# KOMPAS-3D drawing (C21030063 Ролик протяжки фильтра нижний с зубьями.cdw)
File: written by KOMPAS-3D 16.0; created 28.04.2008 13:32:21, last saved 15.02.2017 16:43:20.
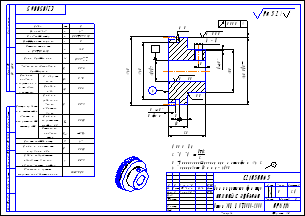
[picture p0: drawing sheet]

Sheet 1: A3, landscape

Title block, sheet 1: name: Ролик протяжки фильтра / нижний с зубьями; designation: C21030063; material: Сталь ХВГ  ГОСТ 5950-2000; mass: 0,2; sheets: 1; organisation: Орими; sheet format: A3; stored path: E:\Рабочая\Чертежи\Невские пороги\C23030129 Шестеня.cdw; drawn by: Баличев Д.С.; drawn by, date: 11.11.14

Views: Вид 1, Вид 3, Местный разрез 1, Спереди, Проекционный вид 4, Вид 5, Изометрия XYZ
Referenced files in D:\: C21030063 Ролик протяжки фильтра нижний с зубьями.m3d
Referenced files in D:\Чертежи\ЧАЙ\C23\: C21030063 Ролик протяжки фильтра нижний с зубьями.m3d
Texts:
  Ra 0,80
  58...62 HRC.
  *Минимальный размер при перешлифовке  46,2.
  Маркировать ID номер - 4193.
  Ra 3,2
  Ra 3,2 ( )
  gliv
  Михаль А.Д.
  ID   4193
  Лит-Масса-Масштаб
  Материал-Предприятие
  Масштаб
  Изм.
  Лист
  № докум.
  Подп.
  Дата
  Лит.
  Разраб.
  Пров.
  Т.контр.
  Листов
  Н.контр.
  Утв.
  ОРИМИ
  Изменение
  Номер документа
  Подпись
  Обозначение документа
  Наименование изделия
  Масса изделия по ГОСТ 2.109-73
  Порядковый номер листа
  Общее количество листов в документе
  Характер работы, выполненной лицом, подписавшим документ
  Наименование или индекс предприятия, выпускающего документ
  Инв. № подл.
  Подп. и дата
  Взам. инв. №
  Инв. № дубл.
  Инвентарный номер подлинника по ГОСТ 2.501-68
  Подпись принявшего подлинник в отдел технической документации
  Инвентарный номер подлинника, взамен которого выпущен данный подлинник
  Инвентарный номер дубликата по ГОСТ 2.502-68
  Подпись принявшего дубликат в отдел технической документации
  Справ. №
  Перв. примен.
  Обозначение документа, взамен или на основании которого выпущен данный документ
  Обозначение документа, в котором впервые записан данный документ
  Подпись лица, копировавшего чертеж
  Обозначение формата листа
Dimensions and other numbers on the sheet: 48; 46,5; 26; 13; 15; 30; 5; -7Н; 6; 3; 40; 0,5; 5 фасок; 1; 0,005; 4; 2:1; 0,2; 11.11.14; 10.03.16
